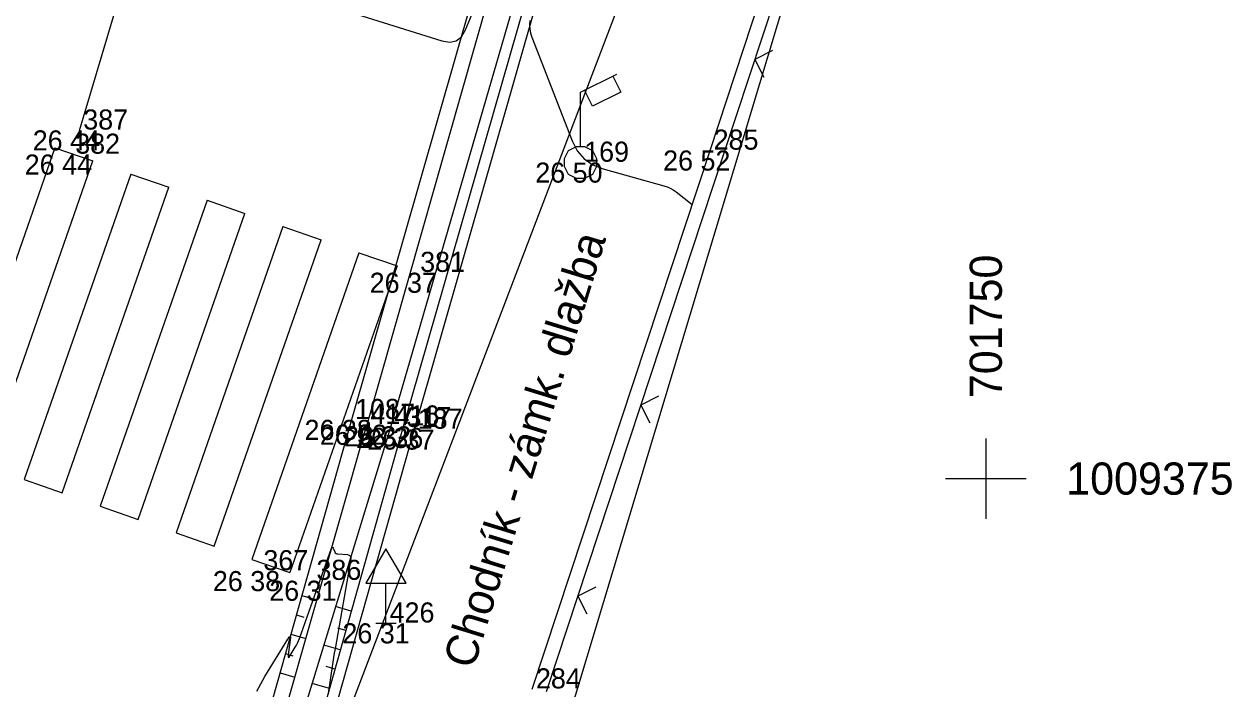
# Model space of a CAD drawing. Extents: x -702257 to -701487, y -1009871 to -1008841.
# Drawn here: x -701761.96 to -701746.94, y -1009377.61 to -1009369.35 of the extents above; entities that cross this region are included whole.
import ezdxf

# ---------------------------------------------------------------- set-up
doc = ezdxf.new("R2010")
doc.units = 0
for name, color, linetype in [('Ex_Minor Contours', 7, 'Continuous'), ('Z_body', 7, 'Continuous'), ('Z_body_cisla', 7, 'Continuous'), ('Z_body_vysky_redukovane', 7, 'Continuous'), ('Z_dopravni_znacky', 7, 'Continuous'), ('Z_hektometricka_sit', 7, 'Continuous'), ('Z_hektometricka_sit_popis', 7, 'Continuous'), ('Z_katastr_hranice', 7, 'Continuous'), ('Z_komunikace', 7, 'Continuous'), ('Z_obruba', 7, 'Continuous'), ('Z_ploty', 7, 'Continuous'), ('Z_ploty_znacky', 7, 'Continuous'), ('Z_popisy', 7, 'Continuous'), ('Z_rozhranni', 7, 'Continuous'), ('Z_site_vo_znaky', 7, 'Continuous'), ('Z_technicke_srafy', 7, 'Continuous'), ('Z_vdz12_plna', 7, 'Continuous'), ('Z_vdz_prechod', 7, 'Continuous'), ('Z_zlabek', 7, 'Continuous')]:
    doc.layers.add(name, color=color, linetype=linetype)

# ---------------------------------------------------------------- blocks, each defined once
blk = doc.blocks.new('Z13_1')
for p, q in [((0, 0.875), (0.45, 1.1)), ((0.4, 1.075), (0.5, 0.875)), ((0, 0.2), (0, 0.875)), ((0.15, 0.7), (0.05, 0.9)), ((0.5, 0.875), (0.15, 0.7)), ((-0.15, 0.15), (-0.05, 0.2)), ((-0.05, 0.2), (0.05, 0.2)), ((0.05, 0.2), (0.15, 0.15)), ((-0.2, 0.05), (-0.15, 0.15)), ((-0.2, -0.05), (-0.2, 0.05)), ((0.15, 0.15), (0.2, 0.05)), ((0.2, 0.05), (0.2, -0.05)), ((-0.15, -0.15), (-0.2, -0.05)), ((-0.05, -0.2), (-0.15, -0.15)), ((0.15, -0.15), (0.05, -0.2)), ((0.2, -0.05), (0.15, -0.15)), ((0.05, -0.2), (-0.05, -0.2))]:
    blk.add_line(p, q)
blk = doc.blocks.new('Z212_1')
for p, q in [((-0.175, 0.175), (0, 0)), ((0, 0), (0.175, 0.175))]:
    blk.add_line(p, q)
blk = doc.blocks.new('Z527_1')
for p, q in [((0, 0.925), (-0.25, 0.5)), ((0.25, 0.5), (0, 0.925)), ((-0.25, 0.5), (0.25, 0.5)), ((0, 0), (0, 0.5)), ((-0.125, 0), (0.125, 0))]:
    blk.add_line(p, q)
blk = doc.blocks.new('Z13_2')
for p, q in [((0, 0.875), (0.45, 1.1)), ((0.4, 1.075), (0.5, 0.875)), ((0, 0.2), (0, 0.875)), ((0.15, 0.7), (0.05, 0.9)), ((0.5, 0.875), (0.15, 0.7)), ((-0.15, 0.15), (-0.05, 0.2)), ((-0.05, 0.2), (0.05, 0.2)), ((0.05, 0.2), (0.15, 0.15)), ((-0.2, 0.05), (-0.15, 0.15)), ((-0.2, -0.05), (-0.2, 0.05)), ((0.15, 0.15), (0.2, 0.05)), ((0.2, 0.05), (0.2, -0.05)), ((-0.15, -0.15), (-0.2, -0.05)), ((-0.05, -0.2), (-0.15, -0.15)), ((0.15, -0.15), (0.05, -0.2)), ((0.2, -0.05), (0.15, -0.15)), ((0.05, -0.2), (-0.05, -0.2))]:
    blk.add_line(p, q)
blk = doc.blocks.new('Z527_2')
for p, q in [((0, 0.925), (-0.25, 0.5)), ((0.25, 0.5), (0, 0.925)), ((-0.25, 0.5), (0.25, 0.5)), ((0, 0), (0, 0.5)), ((-0.125, 0), (0.125, 0))]:
    blk.add_line(p, q)
blk = doc.blocks.new('POINT_DISPLAY')
blk.add_line((0, 0), (0, 0))

msp = doc.modelspace()

# ---------------------------------------------------------------- linework, layer by layer
at = {"layer": 'Ex_Minor Contours'}
for points in [[(-701759.085, -1009368.825), (-701756.764, -1009369.557), (-701756.668, -1009369.573), (-701756.587, -1009369.555), (-701756.522, -1009369.505), (-701756.472, -1009369.421), (-701756.305, -1009369.017)], [(-701755.673, -1009369.304), (-701755.676, -1009369.356), (-701755.672, -1009369.408), (-701755.662, -1009369.46), (-701755.646, -1009369.51), (-701755.145, -1009370.799), (-701755.082, -1009370.923), (-701754.996, -1009371.022), (-701754.889, -1009371.097), (-701754.76, -1009371.148), (-701754.003, -1009371.36), (-701753.963, -1009371.373), (-701753.924, -1009371.39), (-701753.888, -1009371.41), (-701753.853, -1009371.435), (-701753.651, -1009371.59)], [(-701759.068, -1009377.645), (-701759.018, -1009377.553), (-701758.965, -1009377.463), (-701758.682, -1009376.996), (-701758.664, -1009376.97), (-701758.652, -1009376.964), (-701758.648, -1009376.976), (-701758.65, -1009377.007), (-701758.675, -1009377.192), (-701758.676, -1009377.215), (-701758.673, -1009377.224), (-701758.665, -1009377.219), (-701758.651, -1009377.2), (-701758.588, -1009377.098), (-701758.573, -1009377.072), (-701758.559, -1009377.046), (-701758.547, -1009377.018), (-701758.536, -1009376.99), (-701758.139, -1009375.865), (-701758.134, -1009375.856), (-701758.129, -1009375.852), (-701758.124, -1009375.855), (-701758.119, -1009375.864), (-701758.096, -1009375.912), (-701758.09, -1009375.923), (-701758.081, -1009375.931), (-701758.071, -1009375.936), (-701758.058, -1009375.938), (-701757.939, -1009375.946), (-701757.918, -1009375.951), (-701757.904, -1009375.961), (-701757.898, -1009375.976), (-701757.898, -1009375.998), (-701758.093, -1009377.116), (-701758.103, -1009377.171), (-701758.112, -1009377.226), (-701758.121, -1009377.282), (-701758.13, -1009377.337), (-701758.177, -1009377.643)]]:
    msp.add_lwpolyline(points, dxfattribs=at)
at = {"layer": 'Z_hektometricka_sit'}
for p, q in [((-701750, -1009374.5), (-701750, -1009375.5)), ((-701750, -1009374.5), (-701750, -1009375.5)), ((-701750, -1009374.5), (-701750, -1009375.5)), ((-701750.5, -1009375), (-701749.5, -1009375)), ((-701750.5, -1009375), (-701749.5, -1009375)), ((-701750.5, -1009375), (-701749.5, -1009375))]:
    msp.add_line(p, q, dxfattribs=at)
at = {"layer": 'Z_katastr_hranice'}
for p, q in [((-701752.99, -1009364.98), (-701769.49, -1009408.19)), ((-701751.41, -1009365.43), (-701755.31, -1009378.37))]:
    msp.add_line(p, q, dxfattribs=at)
at = {"layer": 'Z_komunikace'}
for p, q in [((-701755, -1009364.2), (-701757.89, -1009374.27)), ((-701757.89, -1009374.27), (-701759.1, -1009378.56))]:
    msp.add_line(p, q, dxfattribs=at)
at = {"layer": 'Z_obruba'}
for p, q in [((-701754.26, -1009364.43), (-701757.11, -1009374.39)), ((-701757.11, -1009374.39), (-701758.37, -1009378.85))]:
    msp.add_line(p, q, dxfattribs=at)
at = {"layer": 'Z_ploty'}
for p, q in [((-701753.43, -1009370.92), (-701751.53, -1009365.17)), ((-701753.43, -1009370.92), (-701751.53, -1009365.17)), ((-701753.264, -1009370.975), (-701751.364, -1009365.225)), ((-701755.64, -1009377.62), (-701753.43, -1009370.92)), ((-701755.64, -1009377.62), (-701753.43, -1009370.92)), ((-701755.465, -1009377.648), (-701753.264, -1009370.975))]:
    msp.add_line(p, q, dxfattribs=at)
at = {"layer": 'Z_rozhranni'}
for p, q in [((-701754.39, -1009364.41), (-701757.25, -1009374.37)), ((-701754.39, -1009364.41), (-701757.25, -1009374.37)), ((-701757.25, -1009374.37), (-701758.52, -1009378.87)), ((-701757.25, -1009374.37), (-701758.52, -1009378.87))]:
    msp.add_line(p, q, dxfattribs=at)
at = {"layer": 'Z_technicke_srafy'}
for p, q in [((-701758.506, -1009376.455), (-701758.32, -1009376.507)), ((-701758.574, -1009376.696), (-701758.481, -1009376.722)), ((-701757.893, -1009376.647), (-701758.087, -1009376.592)), ((-701758.642, -1009376.936), (-701758.457, -1009376.988)), ((-701757.961, -1009376.888), (-701758.06, -1009376.86)), ((-701758.028, -1009377.128), (-701758.233, -1009377.071)), ((-701758.71, -1009377.177), (-701758.618, -1009377.203)), ((-701758.778, -1009377.417), (-701758.594, -1009377.469)), ((-701758.096, -1009377.369), (-701758.202, -1009377.339)), ((-701758.164, -1009377.61), (-701758.38, -1009377.549))]:
    msp.add_line(p, q, dxfattribs=at)
at = {"layer": 'Z_vdz12_plna'}
msp.add_line((-701761.27, -1009370.67), (-701758.73, -1009362.13), dxfattribs=at)
msp.add_line((-701761.27, -1009370.67), (-701758.73, -1009362.13), dxfattribs=at)
at = {"layer": 'Z_vdz_prechod'}
for p, q in [((-701761.577, -1009370.887), (-701762.895, -1009374.663)), ((-701761.577, -1009370.887), (-701761.104, -1009371.05)), ((-701762.43, -1009374.848), (-701761.104, -1009371.05)), ((-701760.632, -1009371.214), (-701761.959, -1009375.013)), ((-701760.632, -1009371.214), (-701760.159, -1009371.377)), ((-701761.487, -1009375.178), (-701760.159, -1009371.377)), ((-701759.686, -1009371.54), (-701761.015, -1009375.343)), ((-701759.686, -1009371.54), (-701759.214, -1009371.703)), ((-701760.543, -1009375.509), (-701759.214, -1009371.703)), ((-701758.741, -1009371.866), (-701760.071, -1009375.674)), ((-701758.741, -1009371.866), (-701758.268, -1009372.03)), ((-701759.599, -1009375.839), (-701758.268, -1009372.03)), ((-701757.796, -1009372.193), (-701759.127, -1009376.005)), ((-701757.796, -1009372.193), (-701757.323, -1009372.356)), ((-701757.323, -1009372.356), (-701758.655, -1009376.17)), ((-701761.959, -1009375.013), (-701761.487, -1009375.178)), ((-701761.015, -1009375.343), (-701760.543, -1009375.509)), ((-701760.071, -1009375.674), (-701759.599, -1009375.839)), ((-701759.127, -1009376.005), (-701758.655, -1009376.17))]:
    msp.add_line(p, q, dxfattribs=at)
at = {"layer": 'Z_zlabek'}
for p, q in [((-701754.83, -1009364.27), (-701757.7, -1009374.33)), ((-701754.83, -1009364.27), (-701757.7, -1009374.33)), ((-701754.5, -1009364.37), (-701757.4, -1009374.35)), ((-701754.5, -1009364.37), (-701757.4, -1009374.35)), ((-701758.99, -1009378.86), (-701757.7, -1009374.33)), ((-701758.99, -1009378.86), (-701757.7, -1009374.33)), ((-701757.4, -1009374.35), (-701758.8, -1009378.92)), ((-701757.4, -1009374.35), (-701758.8, -1009378.92))]:
    msp.add_line(p, q, dxfattribs=at)

# ---------------------------------------------------------------- block references
at = {"layer": 'Z_body'}
for p in [(-701761.27, -1009370.67), (-701761.37, -1009370.97), (-701753.43, -1009370.92), (-701755.04, -1009371.07), (-701757.08, -1009372.44), (-701757.89, -1009374.27), (-701757.7, -1009374.33), (-701757.4, -1009374.35), (-701757.25, -1009374.37), (-701757.11, -1009374.39), (-701759.03, -1009376.15), (-701758.37, -1009376.27), (-701757.46, -1009376.8)]:
    msp.add_blockref('POINT_DISPLAY', p, dxfattribs=at)
at = {"layer": 'Z_dopravni_znacky'}
for name in ['Z527_1', 'Z527_2']:
    msp.add_blockref(name, (-701757.46, -1009376.8), dxfattribs=at)
at = {"layer": 'Z_ploty_znacky', "rotation": -108.30000000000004}
for p in [(-701752.872, -1009369.788), (-701754.29, -1009374.087), (-701755.073, -1009376.461)]:
    msp.add_blockref('Z212_1', p, dxfattribs=at)
at = {"layer": 'Z_site_vo_znaky'}
for name in ['Z13_1', 'Z13_2']:
    msp.add_blockref(name, (-701755.04, -1009371.07), dxfattribs=at)

# ---------------------------------------------------------------- texts
at = {"layer": 'Z_body_cisla'}
for s, p in [('387', (-701761.225, -1009370.66)), ('285', (-701753.385, -1009370.91)), ('382', (-701761.325, -1009370.96)), ('169', (-701754.995, -1009371.06)), ('381', (-701757.035, -1009372.43)), ('108', (-701757.845, -1009374.26)), ('417', (-701757.655, -1009374.32)), ('416', (-701757.355, -1009374.34)), ('317', (-701757.205, -1009374.36)), ('187', (-701757.065, -1009374.38)), ('367', (-701758.985, -1009376.14)), ('386', (-701758.325, -1009376.26)), ('426', (-701757.415, -1009376.79)), ('284', (-701755.595, -1009377.61))]:
    msp.add_text(s, height=0.25, dxfattribs=at).set_placement(p)
at = {"layer": 'Z_body_vysky_redukovane'}
for s, p in [('26 44', (-701761.853, -1009370.92)), ('26 44', (-701761.953, -1009371.22)), ('26 52', (-701754.013, -1009371.17)), ('26 50', (-701755.603, -1009371.32)), ('26 37', (-701757.663, -1009372.69)), ('26 38', (-701758.473, -1009374.52)), ('26 32', (-701758.283, -1009374.58)), ('26 32', (-701757.983, -1009374.6)), ('26 36', (-701757.833, -1009374.62)), ('26 37', (-701757.693, -1009374.64)), ('26 38', (-701759.613, -1009376.4)), ('26 31', (-701758.912, -1009376.52)), ('26 31', (-701758.002, -1009377.05))]:
    msp.add_text(s, height=0.25, dxfattribs=at).set_placement(p)
at = {"layer": 'Z_hektometricka_sit_popis'}
msp.add_text('701750', height=0.4, rotation=90, dxfattribs=at).set_placement((-701749.8, -1009374))
msp.add_text('1009375', height=0.4, dxfattribs=at).set_placement((-701749, -1009375.2))
at = {"layer": 'Z_popisy'}
msp.add_text('Chodník - zámk. dlažba', height=0.4, rotation=72.9, dxfattribs=at).set_placement((-701756.372, -1009377.383))

doc.saveas('drawing.dxf')
